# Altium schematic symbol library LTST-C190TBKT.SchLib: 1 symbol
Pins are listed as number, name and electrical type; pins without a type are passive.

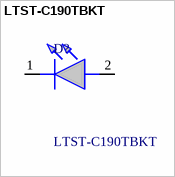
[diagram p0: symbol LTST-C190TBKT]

## LTST-C190TBKT
designator D?
Standard LEDs - SMD Blue Clear 470nm; Manufacturer_Name: Lite-On; Geometry.Height: 0.9mm
footprint LTSTC190TBKT
pins: 1 K, 2 A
